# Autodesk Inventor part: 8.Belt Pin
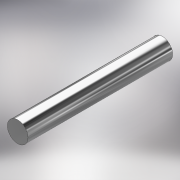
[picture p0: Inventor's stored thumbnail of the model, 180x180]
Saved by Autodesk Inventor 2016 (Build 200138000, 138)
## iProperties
Created: 2016-01
Part Number: 8.Belt Pin
Material: Generic
Document SubType Name: Modeling
Designer: Black Falcon
Density: 1 g/cm^3
Appearance: Chrome - Polished
Author: Black Falcon
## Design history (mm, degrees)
sketch "Sketch1"
  geometry: C1 r 3.81 at (0, 0); 1 further point
  constraints: 1 centre point, 1 coincident
  dimensions: "d0" = 7.62 diameter of C1
extrude "Extrusion1" new body sketch "Sketch1" distance "d1" = 40.64; taper "d2" = 0 deg
sketch "Sketch2"
  geometry: C1 r 3.81 at (0, 0) reference; 1 further point
extrude "Extrusion2" join sketch "Sketch2" distance "d3" = 12.7; taper "d4" = 0 deg
body "Solid1"
node "Projected Loop1"
